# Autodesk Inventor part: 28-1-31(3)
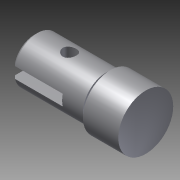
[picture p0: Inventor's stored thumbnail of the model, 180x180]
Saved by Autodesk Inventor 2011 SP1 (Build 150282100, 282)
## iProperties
Created: 2014-01
Part Number: 28-1-31(3)
Document SubType Name: Modeling
Designer: Administrator
Density: 1 g/cm^3
Author: Administrator
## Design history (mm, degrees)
sketch "草图1"
  geometry: L1 (0, 0)-(0, 9); L2 (0, 9)-(1.414, 10.414); L3 (1.414, 10.414)-(32.414, 10.414); L4 (32.414, 10.414)-(32.414, 8.414); L5 (32.414, 8.414)-(34.414, 8.414); L6 (34.414, 8.414)-(34.414, 12.414); L7 (34.414, 12.414)-(50.414, 12.414); L8 (50.414, 12.414)-(50.414, 0); L9 (50.414, 0)-(0, 0)
  constraints: 18 end point, 4 perpendicular, 3 parallel, 1 vertical
  dimensions: "d0" = 9 distance of L1.start L1.end; "d1" = 2 distance of L1.end L2.end; "d2" = 135 deg angle of L1 L2; "d3" = 31 distance of L2.end L3.end; "d4" = 2 distance of L3.end L4.end; "d5" = 2 distance of L4.end L5.end; "d6" = 4 distance of L5.end L6.end; "d7" = 16 distance of L6.end L7.end
revolve "旋转1" sketch "草图1" stored, may be unused: angle "d8" = 90 deg
sketch "草图7"
  geometry: L1 (-2.5, 13.655)-(2.5, 13.655); L2 (2.5, 13.655)-(2.5, -13.655); L3 (2.5, -13.655)-(-2.5, -13.655); L4 (-2.5, -13.655)-(-2.5, 13.655); C1 r 9 at (0, 0) reference; 2 further points
  constraints: 8 end point, 2 midpoint, 2 parallel, 1 horizontal, 1 horizontal alignment, 1 perpendicular, 1 vertical alignment
  dimensions: "d32" = 5 distance of L1.start L1.end
extrude "拉伸3" cut sketch "草图7" distance "d33" = 23; taper "d34" = 0 deg
node "工作平面5"
sketch "草图8"
  geometry: 2 further points
hole "Hole2" sketch "草图8" at (16, 0) diameter "d37" = 6.1; stored, may be unused: countersink angle "d41" = 90 deg, drill point angle "d43" = 118 deg; dims "d38" = 6, "d39" = 4, "d40" = 2, "d42" = 8
node "实体1"
